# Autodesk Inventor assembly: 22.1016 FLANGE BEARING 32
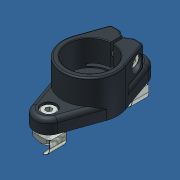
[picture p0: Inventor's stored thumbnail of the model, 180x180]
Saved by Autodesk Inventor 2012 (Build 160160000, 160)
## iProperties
Created: 2013-04
Part Number: 22.1016 FLANGE BEARING 32
Document SubType Name: Assembly
Designer: Admin
Author: Admin
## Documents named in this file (6)
- C:\Andys Backup Data\ANDY'S INVENTOR\INVENTOR LIBRARIES\PARTS LIBRARY\KANBAN SYSTEMS\22.1016 FLANGE BEARING 32.iam
- C:\Andys Backup Data\ANDY'S INVENTOR\INVENTOR LIBRARIES\PARTS LIBRARY\KANBAN SYSTEMS\SUBCOMPONENTS\22.1016 FLANGE BEARING 32.ipt
- C:\Andys Backup Data\ANDY'S INVENTOR\INVENTOR LIBRARIES\PARTS LIBRARY\FASTENING ELEMENTS\SCREWS CAP\21.1238 M6X16.ipt
- C:\Andys Backup Data\ANDY'S INVENTOR\INVENTOR LIBRARIES\PARTS LIBRARY\FASTENING ELEMENTS\NUTS\21.1330_2 M6 SQUARE NUT POS FXG.ipt
- C:\Andys Backup Data\ANDY'S INVENTOR\INVENTOR LIBRARIES\PARTS LIBRARY\FASTENING ELEMENTS\SCREWS CAP\21.1240 M6X20.ipt
- C:\Andys Backup Data\ANDY'S INVENTOR\INVENTOR LIBRARIES\PARTS LIBRARY\KANBAN SYSTEMS\SUBCOMPONENTS\22.1016 M6 LOCKNUT.ipt
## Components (7 placed, 5 different names)
1. 22.1016 FLANGE BEARING 32:1 — Insert:1, Insert:2, Mate:3, Mate:4, Angle:2, Insert:3, Mate:6, Angle:3
2. 21.1238  M6 x 16:1 — Insert:2, Mate:2
3. 21.1238  M6 x 16:2 — Insert:1, Mate:1
4. 21.1330_2 M6 SQUARE NUT POS FXG:1 — Mate:1, Mate:4, Angle:1, Angle:2
5. 21.1330_2 M6 SQUARE NUT POS FXG:2 — Mate:2, Mate:3, Angle:1
6. 21.1240  M6 x 20:1 — Insert:3, Mate:5
7. 22.1016 M6 LOCKNUT:1 — Mate:5, Mate:6, Angle:3
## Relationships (12: Mate 6, Insert 3, Angle 3)
- Insert:1: 22.1016 FLANGE BEARING 32:1 ↔ 21.1238  M6 x 16:2
- Insert:2: 22.1016 FLANGE BEARING 32:1 ↔ 21.1238  M6 x 16:1
- Mate:1: 21.1238  M6 x 16:2 ↔ 21.1330_2 M6 SQUARE NUT POS FXG:1
- Mate:2: 21.1238  M6 x 16:1 ↔ 21.1330_2 M6 SQUARE NUT POS FXG:2
- Mate:3: 22.1016 FLANGE BEARING 32:1 ↔ 21.1330_2 M6 SQUARE NUT POS FXG:2
- Mate:4: 22.1016 FLANGE BEARING 32:1 ↔ 21.1330_2 M6 SQUARE NUT POS FXG:1
- Angle:1: 21.1330_2 M6 SQUARE NUT POS FXG:1 ↔ 21.1330_2 M6 SQUARE NUT POS FXG:2
- Angle:2: 22.1016 FLANGE BEARING 32:1 ↔ 21.1330_2 M6 SQUARE NUT POS FXG:1
- Insert:3: 22.1016 FLANGE BEARING 32:1 ↔ 21.1240  M6 x 20:1
- Mate:5: 21.1240  M6 x 20:1 ↔ 22.1016 M6 LOCKNUT:1
- Mate:6: 22.1016 FLANGE BEARING 32:1 ↔ 22.1016 M6 LOCKNUT:1
- Angle:3: 22.1016 FLANGE BEARING 32:1 ↔ 22.1016 M6 LOCKNUT:1
